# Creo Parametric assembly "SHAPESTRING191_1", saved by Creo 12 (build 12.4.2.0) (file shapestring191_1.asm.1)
Units: Custom; MM, KILOGRAM, SECS

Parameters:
  PTC_WM_ITERATION = "0"
  PTC_WM_VERSION = "-.0"
  PTC_WM_LIFECYCLE_STATE = "In Work"
  PTC_WM_LIFECYCLE = "MO_CADDocument"
  PTC_WM_CREATED_BY = "Maximilian Roepper (Z0017RMS: MO)"
  PTC_WM_CREATED_ON = "18-Sep-26 11:36:42 AM"
  PTC_WM_MODIFIED_BY = "Maximilian Roepper (Z0017RMS: MO)"
  PTC_WM_MODIFIED_ON = "18-Sep-26 11:36:46 AM"
  PDMLINKNUMBER = "PDM000071455146"
  PTC_WM_NUMBER = "PDM000071455146"

Other parameters: WEIGHT, WEIGHT_FACTOR, WEIGHT_ADD, MC_ERRORS, SUPPLIER

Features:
  1. coordinate system
  2. imported feature
  3. component "SHAPESTRING084_1"
  4. component "SHAPESTRING185_1"
  5. component "SHAPESTRING186_1"
  6. component "SHAPESTRING187_1"
  7. component "SHAPESTRING188_1"
  8. component "SHAPESTRING189_1"
  9. component "SHAPESTRING190_1"

Other named items: DRW_VIEW_ORG, ROUGH-GROB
